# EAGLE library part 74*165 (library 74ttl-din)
8-bit parallel load SHIFT REGISTER
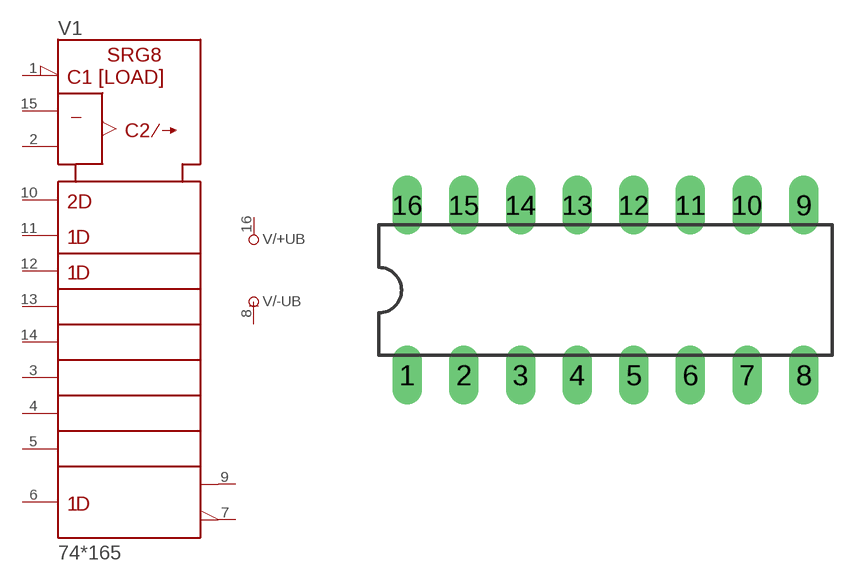
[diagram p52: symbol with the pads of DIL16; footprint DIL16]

Designator prefix V; gates /+UB=+UB /-UB=-UB 1=165

## 74165N  [DIL16]
1  1:SH/LD\  in
2  1:CLK  in
3  1:E  in
4  1:F  in
5  1:G  in
6  1:H  in
7  1:Q\H  out
8  /-UB:-UB  pwr
9  1:QH  out
10  1:SER  in
11  1:A  in
12  1:B  in
13  1:C  in
14  1:D  in
15  1:CLK_INH  in
16  /+UB:+UB  pwr

## Footprint DIL16 (pad centres in mm)
Dual In Line Package
drill 0.813 long: 1 -8.89,-3.81; 2 -6.35,-3.81; 3 -3.81,-3.81; 4 -1.27,-3.81; 5 1.27,-3.81; 6 3.81,-3.81; 7 6.35,-3.81; 8 8.89,-3.81; 9 8.89,3.81; 10 6.35,3.81; 11 3.81,3.81; 12 1.27,3.81; 13 -1.27,3.81; 14 -3.81,3.81; 15 -6.35,3.81; 16 -8.89,3.81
